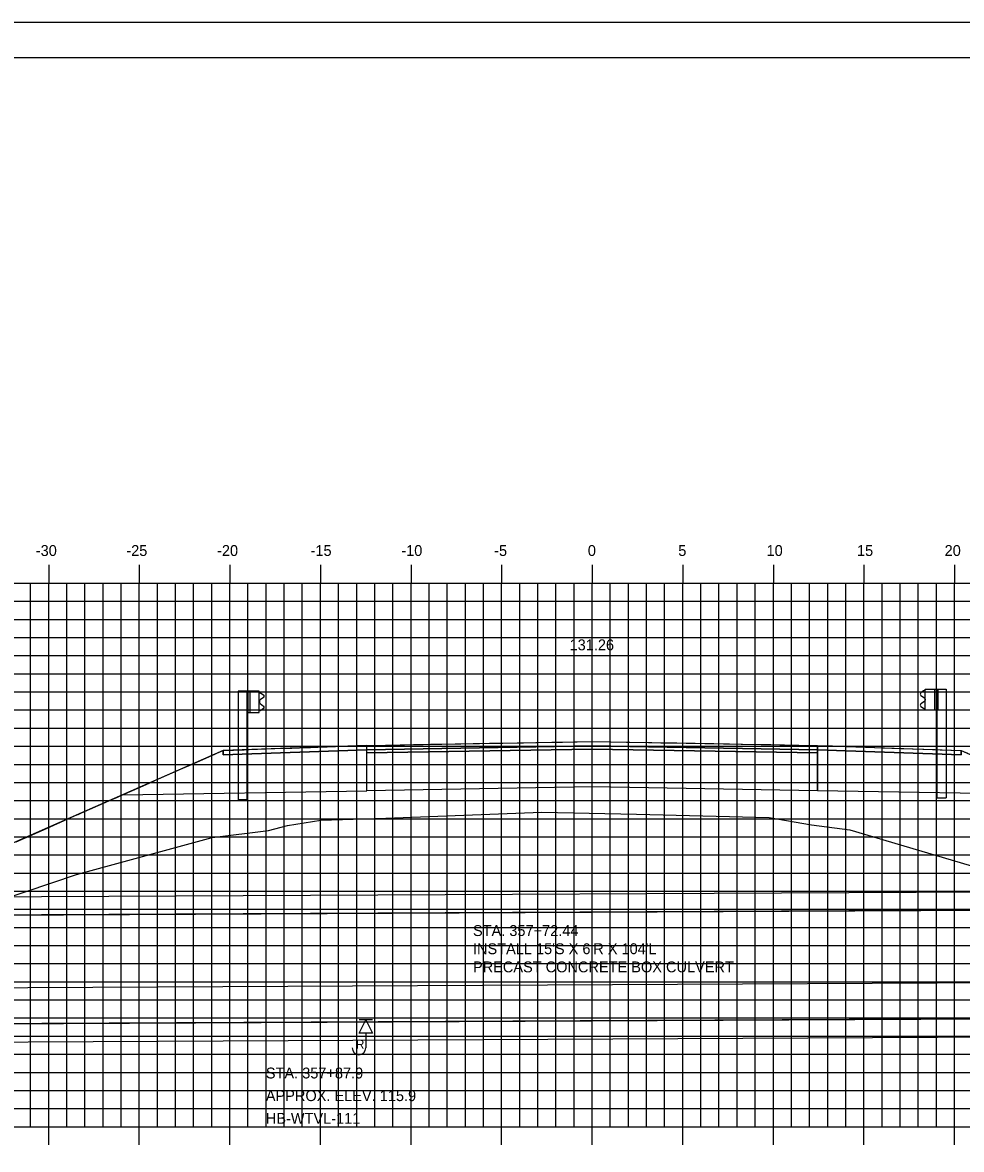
# Model space of a CAD drawing. Extents: x 1145859 to 1146029, y 608981 to 609091.
# Drawn here: x 1145911 to 1145962.8, y 609029.1 to 609091.3 of the extents above; entities that cross this region are included whole.
import ezdxf

# ---------------------------------------------------------------- set-up
doc = ezdxf.new("R2010")
doc.units = 0
for name, color, linetype in [('ANNOTATION', 7, 'Continuous'), ('BORDER', 7, 'Continuous'), ('D_Drainage_Culvert', 7, 'Continuous'), ('D_Guardrail_Beam_Lt', 7, 'Continuous'), ('D_Guardrail_Beam_Rt', 7, 'Continuous'), ('D_Guardrail_ConcBarrier', 7, 'Continuous'), ('D_Roadway_Centerline', 7, 'Continuous'), ('D_Roadway_Centerline_Text', 7, 'Continuous'), ('D_Roadway_Edge_Shoulder', 7, 'Continuous'), ('D_Roadway_Edge_TW', 7, 'Continuous'), ('D_Roadway_Pavement', 7, 'Continuous'), ('D_Roadway_SlopeLines', 7, 'Continuous'), ('D_Roadway_SubGrade', 7, 'Continuous'), ('H_V ANNOTATION', 7, 'Continuous'), ('MAJOR', 7, 'Continuous'), ('MINOR', 7, 'Continuous'), ('PATTERNING', 7, 'Continuous'), ('PLOT BOUNDARY', 7, 'Continuous'), ('ROCKS', 7, 'Continuous'), ('S_Roadway_Centerline', 7, 'Continuous')]:
    doc.layers.add(name, color=color, linetype=linetype)

msp = doc.modelspace()

# ---------------------------------------------------------------- linework, layer by layer
msp.add_lwpolyline([(1145910.608, 609046.064), (1145912.107, 609046.725), (1145912.317, 609046.817), (1145914.001, 609047.56), (1145914.022, 609047.569), (1145914.209, 609047.651), (1145915.895, 609048.395), (1145916.157, 609048.511), (1145916.472, 609048.649), (1145917.454, 609049.083), (1145917.788, 609049.23), (1145918.468, 609049.53), (1145919.682, 609050.066), (1145920.279, 609050.329), (1145921.576, 609050.901), (1145921.692, 609050.953), (1145922.035, 609051.104), (1145922.035, 609051.104), (1145922.036, 609051.104), (1145923.193, 609051.144), (1145923.469, 609051.154), (1145923.92, 609051.169), (1145925.363, 609051.219), (1145925.821, 609051.235), (1145926.241, 609051.25), (1145926.86, 609051.271), (1145927.257, 609051.285), (1145927.778, 609051.303), (1145929.151, 609051.351), (1145929.956, 609051.379), (1145931.044, 609051.398), (1145932.544, 609051.424), (1145932.938, 609051.431), (1145933.473, 609051.44), (1145934.832, 609051.464), (1145935.831, 609051.481), (1145936.725, 609051.497), (1145937.475, 609051.51), (1145938.619, 609051.53), (1145940.174, 609051.557), (1145940.513, 609051.563), (1145940.762, 609051.567), (1145942.402, 609051.596), (1145942.406, 609051.596), (1145942.406, 609051.596), (1145942.407, 609051.596), (1145944.3, 609051.563), (1145945.693, 609051.538), (1145946.194, 609051.529), (1145947.082, 609051.513), (1145947.617, 609051.504), (1145947.881, 609051.499), (1145948.088, 609051.496), (1145949.108, 609051.478), (1145949.981, 609051.462), (1145950.624, 609051.451), (1145951.875, 609051.429), (1145952.267, 609051.422), (1145953.769, 609051.396), (1145954.847, 609051.377), (1145955.662, 609051.349), (1145957.033, 609051.301), (1145957.556, 609051.282), (1145958.407, 609051.253), (1145959.45, 609051.216), (1145960.09, 609051.194), (1145961.343, 609051.15), (1145961.618, 609051.14), (1145962.768, 609051.1), (1145963.118, 609050.946)])
at = {"layer": 'BORDER'}
msp.add_lwpolyline([(1145867.402, 608984.335), (1146027.402, 608984.335), (1146027.402, 609089.335), (1145867.402, 609089.335)], close=True, dxfattribs=at)
at = {"layer": 'D_Drainage_Culvert'}
for points in [[(1145889.737, 609034.915), (1145993.735, 609035.435), (1145993.695, 609043.435), (1145889.697, 609042.915)], [(1145889.732, 609035.915), (1145993.73, 609036.435), (1145993.7, 609042.435), (1145889.702, 609041.915)]]:
    msp.add_lwpolyline(points, close=True, dxfattribs=at)
at = {"layer": 'D_Guardrail_Beam_Lt'}
for p, q in [((1145922.869, 609054.37), (1145922.869, 609048.37)), ((1145923.34, 609054.37), (1145922.869, 609054.37)), ((1145924.027, 609054.37), (1145923.34, 609054.37)), ((1145923.34, 609054.37), (1145923.34, 609053.203)), ((1145923.402, 609054.37), (1145923.402, 609053.203)), ((1145923.507, 609054.37), (1145923.507, 609053.203)), ((1145924.027, 609053.203), (1145924.027, 609054.37)), ((1145924.027, 609054.286), (1145924.102, 609054.272)), ((1145924.032, 609053.822), (1145924.032, 609053.751)), ((1145924.261, 609054.022), (1145924.066, 609053.886)), ((1145924.117, 609054.265), (1145924.261, 609054.165)), ((1145923.34, 609053.203), (1145924.027, 609053.203)), ((1145923.361, 609048.37), (1145923.361, 609053.203)), ((1145924.102, 609053.301), (1145924.027, 609053.286)), ((1145924.066, 609053.687), (1145924.261, 609053.551)), ((1145924.261, 609053.408), (1145924.117, 609053.308)), ((1145923.361, 609048.37), (1145922.869, 609048.37))]:
    msp.add_line(p, q, dxfattribs=at)
for centre, major_axis, start_param, end_param in [((1145924.111, 609053.822), (-0.0789, 0), 5.323254, 6.283185), ((1145924.094, 609054.231), (0.0417, 0), 0.959931, 1.376053), ((1145924.211, 609054.094), (0.0877, 0), 5.323254, 7.243116), ((1145924.111, 609053.751), (-0.0789, 0), 6.283185, 7.243116), ((1145924.094, 609053.342), (0.0417, 0), 4.907132, 5.323254), ((1145924.211, 609053.479), (0.0877, 0), 5.323254, 7.243116)]:
    msp.add_ellipse(centre, major_axis=major_axis, ratio=0.995501, start_param=start_param, end_param=end_param, dxfattribs=at)
at = {"layer": 'D_Guardrail_Beam_Rt'}
for p, q in [((1145960.696, 609054.383), (1145960.552, 609054.283)), ((1145960.786, 609054.404), (1145960.711, 609054.39)), ((1145960.552, 609054.14), (1145960.748, 609054.004)), ((1145960.748, 609053.805), (1145960.552, 609053.669)), ((1145960.781, 609053.939), (1145960.781, 609053.869)), ((1145960.552, 609053.526), (1145960.696, 609053.426)), ((1145960.711, 609053.419), (1145960.786, 609053.404))]:
    msp.add_line(p, q, dxfattribs=at)
for centre, major_axis, start_param, end_param in [((1145960.72, 609054.349), (-0.0417, 0), 4.907132, 5.323254), ((1145960.602, 609054.212), (-0.0877, 0), 5.323254, 7.243116), ((1145960.702, 609053.939), (0.0789, 0), 0, 0.959931), ((1145960.702, 609053.869), (0.0789, 0), 5.323254, 6.283185), ((1145960.602, 609053.597), (-0.0877, 0), 5.323254, 7.243116), ((1145960.72, 609053.46), (-0.0417, 0), 0.959931, 1.376053)]:
    msp.add_ellipse(centre, major_axis=major_axis, ratio=0.995501, start_param=start_param, end_param=end_param, dxfattribs=at)
at = {"layer": 'D_Guardrail_ConcBarrier'}
for p, q in [((1145960.786, 609054.488), (1145961.473, 609054.488)), ((1145960.786, 609053.321), (1145960.786, 609054.488)), ((1145961.306, 609054.488), (1145961.306, 609053.321)), ((1145961.411, 609054.488), (1145961.411, 609053.321)), ((1145961.473, 609054.488), (1145961.944, 609054.488)), ((1145961.473, 609054.488), (1145961.473, 609053.321)), ((1145961.944, 609054.488), (1145961.944, 609048.488)), ((1145961.473, 609053.321), (1145960.786, 609053.321)), ((1145961.452, 609048.488), (1145961.452, 609053.321)), ((1145961.452, 609048.488), (1145961.944, 609048.488))]:
    msp.add_line(p, q, dxfattribs=at)
at = {"layer": 'D_Roadway_Edge_Shoulder'}
for points in [[(1145929.956, 609051.38), (1145922.036, 609051.105), (1145922.036, 609050.855), (1145929.956, 609051.13)], [(1145954.848, 609051.379), (1145962.768, 609051.102), (1145962.768, 609050.852), (1145954.848, 609051.129)]]:
    msp.add_lwpolyline(points, close=True, dxfattribs=at)
at = {"layer": 'D_Roadway_Edge_TW'}
msp.add_lwpolyline([(1145929.956, 609051.13), (1145929.956, 609051.38), (1145942.402, 609051.597), (1145954.848, 609051.379), (1145954.848, 609051.129), (1145942.402, 609051.347)], close=True, dxfattribs=at)
at = {"layer": 'D_Roadway_Pavement'}
msp.add_lwpolyline([(1145929.956, 609050.964), (1145929.956, 609051.13), (1145942.402, 609051.347), (1145954.848, 609051.129), (1145954.848, 609050.962), (1145942.402, 609051.181)], close=True, dxfattribs=at)
at = {"layer": 'D_Roadway_SlopeLines'}
for points in [[(1145916.472, 609048.651), (1145914.209, 609047.653)], [(1145914.209, 609047.653), (1145892.142, 609037.927)]]:
    msp.add_lwpolyline(points, dxfattribs=at)
at = {"layer": 'D_Roadway_SubGrade'}
for points in [[(1145929.956, 609050.964), (1145929.956, 609051.13), (1145922.036, 609050.855), (1145922.036, 609051.105), (1145922.035, 609051.105), (1145916.472, 609048.651), (1145929.956, 609048.88)], [(1145929.956, 609048.88), (1145929.956, 609050.964), (1145942.402, 609051.181), (1145954.848, 609050.962), (1145954.848, 609048.879), (1145942.402, 609049.097)], [(1145954.848, 609050.962), (1145954.848, 609051.129), (1145962.768, 609050.852), (1145962.768, 609051.102), (1145962.768, 609051.102), (1145968.331, 609048.645), (1145954.848, 609048.879)]]:
    msp.add_lwpolyline(points, close=True, dxfattribs=at)
at = {"layer": 'MAJOR'}
for p, q in [((1145912.402, 609061.337), (1145912.402, 609060.335)), ((1145917.402, 609061.337), (1145917.402, 609060.335)), ((1145922.402, 609061.337), (1145922.402, 609060.335)), ((1145927.402, 609061.337), (1145927.402, 609060.335)), ((1145932.402, 609061.337), (1145932.402, 609060.335)), ((1145937.402, 609061.337), (1145937.402, 609060.335)), ((1145942.402, 609061.337), (1145942.402, 609060.335)), ((1145947.402, 609061.337), (1145947.402, 609060.335)), ((1145952.402, 609061.337), (1145952.402, 609060.335)), ((1145957.402, 609061.337), (1145957.402, 609060.335)), ((1145962.402, 609061.337), (1145962.402, 609060.335)), ((1145872.402, 609060.335), (1146012.402, 609060.335)), ((1145872.402, 609060.335), (1146012.402, 609060.335)), ((1145912.402, 609030.335), (1145912.402, 609060.335)), ((1145917.402, 609030.335), (1145917.402, 609060.335)), ((1145922.402, 609030.335), (1145922.402, 609060.335)), ((1145927.402, 609030.335), (1145927.402, 609060.335)), ((1145932.402, 609030.335), (1145932.402, 609060.335)), ((1145937.402, 609030.335), (1145937.402, 609060.335)), ((1145942.402, 609030.335), (1145942.402, 609060.335)), ((1145947.402, 609030.335), (1145947.402, 609060.335)), ((1145952.402, 609030.335), (1145952.402, 609060.335)), ((1145957.402, 609030.335), (1145957.402, 609060.335)), ((1145962.402, 609030.335), (1145962.402, 609060.335)), ((1145872.402, 609055.335), (1146012.402, 609055.335)), ((1145872.402, 609050.335), (1146012.402, 609050.335)), ((1145872.402, 609045.335), (1146012.402, 609045.335)), ((1145872.402, 609040.335), (1146012.402, 609040.335)), ((1145872.402, 609035.335), (1146012.402, 609035.335)), ((1145872.402, 609030.335), (1146012.402, 609030.335)), ((1145872.402, 609030.335), (1146012.402, 609030.335)), ((1145912.402, 609029.333), (1145912.402, 609030.335)), ((1145917.402, 609029.333), (1145917.402, 609030.335)), ((1145922.402, 609029.333), (1145922.402, 609030.335)), ((1145927.402, 609029.333), (1145927.402, 609030.335)), ((1145932.402, 609029.333), (1145932.402, 609030.335)), ((1145937.402, 609029.333), (1145937.402, 609030.335)), ((1145942.402, 609029.333), (1145942.402, 609030.335)), ((1145947.402, 609029.333), (1145947.402, 609030.335)), ((1145952.402, 609029.333), (1145952.402, 609030.335)), ((1145957.402, 609029.333), (1145957.402, 609030.335)), ((1145962.402, 609029.333), (1145962.402, 609030.335))]:
    msp.add_line(p, q, dxfattribs=at)
at = {"layer": 'MINOR'}
for p, q in [((1145911.402, 609030.335), (1145911.402, 609060.335)), ((1145913.402, 609030.335), (1145913.402, 609060.335)), ((1145914.402, 609030.335), (1145914.402, 609060.335)), ((1145915.402, 609030.335), (1145915.402, 609060.335)), ((1145916.402, 609030.335), (1145916.402, 609060.335)), ((1145918.402, 609030.335), (1145918.402, 609060.335)), ((1145919.402, 609030.335), (1145919.402, 609060.335)), ((1145920.402, 609030.335), (1145920.402, 609060.335)), ((1145921.402, 609030.335), (1145921.402, 609060.335)), ((1145923.402, 609030.335), (1145923.402, 609060.335)), ((1145924.402, 609030.335), (1145924.402, 609060.335)), ((1145925.402, 609030.335), (1145925.402, 609060.335)), ((1145926.402, 609030.335), (1145926.402, 609060.335)), ((1145928.402, 609030.335), (1145928.402, 609060.335)), ((1145929.402, 609030.335), (1145929.402, 609060.335)), ((1145930.402, 609030.335), (1145930.402, 609060.335)), ((1145931.402, 609030.335), (1145931.402, 609060.335)), ((1145933.402, 609030.335), (1145933.402, 609060.335)), ((1145934.402, 609030.335), (1145934.402, 609060.335)), ((1145935.402, 609030.335), (1145935.402, 609060.335)), ((1145936.402, 609030.335), (1145936.402, 609060.335)), ((1145938.402, 609030.335), (1145938.402, 609060.335)), ((1145939.402, 609030.335), (1145939.402, 609060.335)), ((1145940.402, 609030.335), (1145940.402, 609060.335)), ((1145941.402, 609030.335), (1145941.402, 609060.335)), ((1145943.402, 609030.335), (1145943.402, 609060.335)), ((1145944.402, 609030.335), (1145944.402, 609060.335)), ((1145945.402, 609030.335), (1145945.402, 609060.335)), ((1145946.402, 609030.335), (1145946.402, 609060.335)), ((1145948.402, 609030.335), (1145948.402, 609060.335)), ((1145949.402, 609030.335), (1145949.402, 609060.335)), ((1145950.402, 609030.335), (1145950.402, 609060.335)), ((1145951.402, 609030.335), (1145951.402, 609060.335)), ((1145953.402, 609030.335), (1145953.402, 609060.335)), ((1145954.402, 609030.335), (1145954.402, 609060.335)), ((1145955.402, 609030.335), (1145955.402, 609060.335)), ((1145956.402, 609030.335), (1145956.402, 609060.335)), ((1145958.402, 609030.335), (1145958.402, 609060.335)), ((1145959.402, 609030.335), (1145959.402, 609060.335)), ((1145960.402, 609030.335), (1145960.402, 609060.335)), ((1145961.402, 609030.335), (1145961.402, 609060.335)), ((1145872.402, 609059.335), (1146012.402, 609059.335)), ((1145872.402, 609058.335), (1146012.402, 609058.335)), ((1145872.402, 609057.335), (1146012.402, 609057.335)), ((1145872.402, 609056.335), (1146012.402, 609056.335)), ((1145872.402, 609054.335), (1146012.402, 609054.335)), ((1145872.402, 609053.335), (1146012.402, 609053.335)), ((1145872.402, 609052.335), (1146012.402, 609052.335)), ((1145872.402, 609051.335), (1146012.402, 609051.335)), ((1145872.402, 609049.335), (1146012.402, 609049.335)), ((1145872.402, 609048.335), (1146012.402, 609048.335)), ((1145872.402, 609047.335), (1146012.402, 609047.335)), ((1145872.402, 609046.335), (1146012.402, 609046.335)), ((1145872.402, 609044.335), (1146012.402, 609044.335)), ((1145872.402, 609043.335), (1146012.402, 609043.335)), ((1145872.402, 609042.335), (1146012.402, 609042.335)), ((1145872.402, 609041.335), (1146012.402, 609041.335)), ((1145872.402, 609039.335), (1146012.402, 609039.335)), ((1145872.402, 609038.335), (1146012.402, 609038.335)), ((1145872.402, 609037.335), (1146012.402, 609037.335)), ((1145872.402, 609036.335), (1146012.402, 609036.335)), ((1145872.402, 609034.335), (1146012.402, 609034.335)), ((1145872.402, 609033.335), (1146012.402, 609033.335)), ((1145872.402, 609032.335), (1146012.402, 609032.335)), ((1145872.402, 609031.335), (1146012.402, 609031.335))]:
    msp.add_line(p, q, dxfattribs=at)
at = {"layer": 'PATTERNING'}
for p, q in [((1145889.702, 609041.915), (1145993.7, 609042.435)), ((1145993.73, 609036.435), (1145889.732, 609035.915)), ((1145889.732, 609035.915), (1145993.732, 609036.435))]:
    msp.add_line(p, q, dxfattribs=at)
for points in [[(1145993.695, 609043.435), (1145889.697, 609042.915), (1145889.702, 609041.915)], [(1145889.737, 609034.915), (1145993.735, 609035.435), (1145993.73, 609036.435)]]:
    msp.add_lwpolyline(points, dxfattribs=at)
msp.add_lwpolyline([(1145889.732, 609035.915), (1145889.722, 609037.915), (1145993.72, 609038.435), (1145993.73, 609036.435)], close=True, dxfattribs=at)
at = {"layer": 'PLOT BOUNDARY'}
msp.add_lwpolyline([(1145859.308, 608981.276), (1146029.308, 608981.276), (1146029.308, 609091.276), (1145859.308, 609091.276)], close=True, dxfattribs=at)
at = {"layer": 'ROCKS'}
for p, q in [((1145930.271, 609036.235), (1145929.533, 609036.235)), ((1145929.902, 609035.497), (1145929.902, 609034.682))]:
    msp.add_line(p, q, dxfattribs=at)
msp.add_lwpolyline([(1145929.902, 609036.235), (1145930.271, 609035.497), (1145929.533, 609035.497)], close=True, dxfattribs=at)
msp.add_arc((1145929.529, 609034.682), 0.373, 180, 0, dxfattribs=at)
at = {"layer": 'S_Roadway_Centerline'}
msp.add_lwpolyline([(1145906.881, 609041.89), (1145913.944, 609044.257), (1145921.422, 609046.302), (1145924.54, 609046.675), (1145925.589, 609046.967), (1145927.425, 609047.251), (1145931.02, 609047.367), (1145939.621, 609047.687), (1145944.852, 609047.586), (1145952.173, 609047.399), (1145954.502, 609046.988), (1145956.617, 609046.711), (1145970.97, 609042.471)], dxfattribs=at)

# ---------------------------------------------------------------- texts
at = {"layer": 'ANNOTATION'}
for s, p in [('STA. 357+72.44', (1145935.822, 609040.859)), ("INSTALL 15'S X 6'R X 104'L", (1145935.822, 609039.857)), ('PRECAST CONCRETE BOX CULVERT', (1145935.822, 609038.855))]:
    msp.add_text(s, height=0.6, dxfattribs=at).set_placement(p)
at = {"layer": 'D_Roadway_Centerline'}
for s, p in [('C', (1145942.396, 609051.597)), ('L', (1145942.402, 609051.59))]:
    msp.add_text(s, height=0.0146, dxfattribs=at).set_placement(p)
at = {"layer": 'D_Roadway_Centerline_Text'}
msp.add_text('131.26', height=0.6, dxfattribs=at).set_placement((1145941.155, 609056.629))
at = {"layer": 'H_V ANNOTATION'}
for s, p in [('-30', (1145911.69, 609061.835)), ('-25', (1145916.687, 609061.835)), ('-20', (1145921.695, 609061.835)), ('-15', (1145926.858, 609061.835)), ('-10', (1145931.866, 609061.835)), ('-5', (1145936.992, 609061.835)), ('0', (1145942.161, 609061.835)), ('5', (1145947.153, 609061.835)), ('10', (1145952.027, 609061.835)), ('15', (1145957.019, 609061.835)), ('20', (1145961.856, 609061.835))]:
    msp.add_text(s, height=0.6, dxfattribs=at).set_placement(p)
at = {"layer": 'ROCKS'}
msp.add_text('R', height=0.492, dxfattribs=at).set_placement((1145929.356, 609034.639))
for s, p in [('STA. 357+87.9', (1145924.388, 609032.998)), ('APPROX. ELEV. 115.9', (1145924.388, 609031.748)), ('HB-WTVL-111', (1145924.388, 609030.498))]:
    msp.add_text(s, height=0.6, rotation=360, dxfattribs=at).set_placement(p)
at = {"layer": 'S_Roadway_Centerline'}
for s, p in [('L', (1145939.613, 609047.68)), ('C', (1145939.616, 609047.687))]:
    msp.add_text(s, height=0.0146, dxfattribs=at).set_placement(p)

doc.saveas('drawing.dxf')
